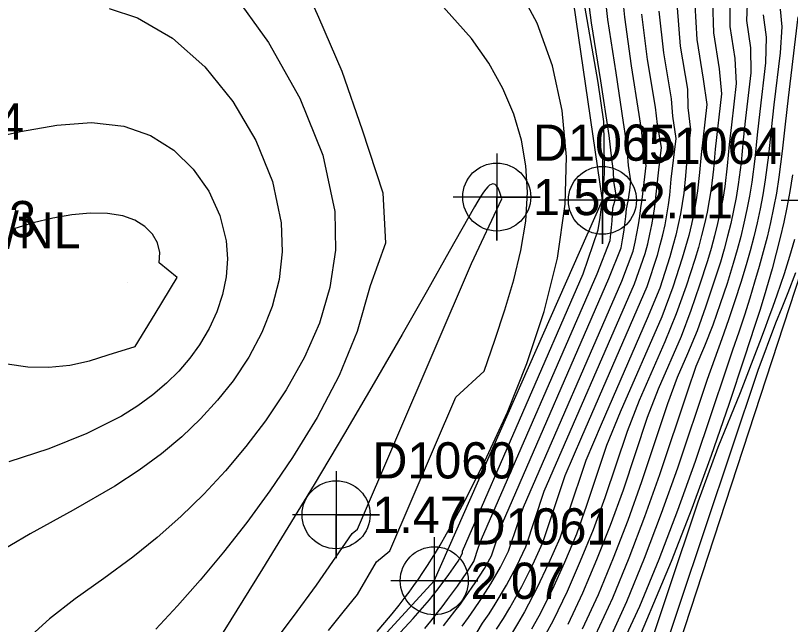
# Model space of a CAD drawing. Extents: x 2356077 to 2359823, y 225951 to 227822.
# Drawn here: x 2357294.1 to 2357347.5, y 226641.4 to 226683.4 of the extents above; entities that cross this region are included whole.
import ezdxf

# ---------------------------------------------------------------- set-up
doc = ezdxf.new("R2010")
doc.units = 0
for name, color, linetype in [('DTM Contours Major', 7, 'Continuous'), ('DTM Contours Minor', 7, 'Continuous'), ('Exist DTM Breakline', 7, 'Continuous'), ('Exist DTM Breakline Cogo Elevation', 7, 'Continuous'), ('Exist DTM Breakline Cogo Number', 7, 'Continuous'), ('Exist DTM Breakline Cogo Point CELL', 7, 'Continuous'), ('Exist DTM Regular Point CELL', 7, 'Continuous'), ('Exist DTM Regular Point Cogo Comment', 7, 'Continuous'), ('Exist DTM Regular Point Cogo Elevation', 7, 'Continuous'), ('Exist DTM Regular Point Cogo Number', 7, 'Continuous'), ('PH Exist DTM Point', 7, 'Continuous')]:
    doc.layers.add(name, color=color, linetype=linetype)

msp = doc.modelspace()

# ---------------------------------------------------------------- linework, layer by layer
at = {"layer": 'DTM Contours Major'}
for points in [[(2357319.049, 226640.927), (2357319.587, 226641.554), (2357320.091, 226642.163), (2357320.565, 226642.756), (2357320.915, 226643.208), (2357321.252, 226643.656), (2357321.578, 226644.103), (2357321.897, 226644.554), (2357322.21, 226645.013), (2357322.52, 226645.482), (2357322.956, 226646.169), (2357323.395, 226646.892), (2357323.842, 226647.66), (2357324.301, 226648.477), (2357324.776, 226649.353), (2357325.272, 226650.294), (2357326.622, 226652.988), (2357328.026, 226656.06), (2357329.375, 226659.424), (2357330.563, 226662.994), (2357331.482, 226666.682), (2357332.023, 226670.402), (2357332.112, 226673.676), (2357331.817, 226676.87), (2357331.138, 226679.948), (2357330.075, 226682.872), (2357328.628, 226685.605)], [(2357309.005, 226685.105), (2357311.567, 226681.55), (2357313.727, 226677.722), (2357315.307, 226673.785), (2357316.129, 226669.9), (2357316.175, 226667.223), (2357315.801, 226664.656), (2357315.07, 226662.199), (2357314.043, 226659.849), (2357312.783, 226657.607), (2357311.352, 226655.472), (2357310.01, 226653.701), (2357308.59, 226652.01), (2357307.095, 226650.401), (2357305.529, 226648.872), (2357303.898, 226647.426), (2357302.204, 226646.061), (2357300.2, 226644.584), (2357298.243, 226643.18), (2357296.461, 226641.814), (2357294.977, 226640.449), (2357293.906, 226639.06)], [(2357343.37, 226684.574), (2357343.373, 226682.645), (2357343.707, 226680.456), (2357343.809, 226678.734), (2357343.469, 226675.883), (2357343.31, 226674.517), (2357343.187, 226673.047), (2357343.009, 226671.613), (2357342.87, 226670.754), (2357342.708, 226669.904), (2357342.523, 226669.058), (2357342.314, 226668.209), (2357342.081, 226667.354), (2357341.825, 226666.487), (2357341.282, 226664.808), (2357340.668, 226663.069), (2357339.999, 226661.272), (2357338.425, 226657.649), (2357337.674, 226655.683), (2357336.003, 226650.689), (2357335.109, 226648.257), (2357334.173, 226645.873), (2357333.202, 226643.577), (2357332.188, 226641.412)], [(2357325.953, 226640.89), (2357326.319, 226641.502), (2357326.764, 226642.164), (2357327.187, 226642.827), (2357327.96, 226644.135), (2357328.677, 226645.466), (2357329.29, 226646.775), (2357330.574, 226650.611), (2357336.783, 226664.908), (2357337.534, 226667.007), (2357337.702, 226667.675), (2357337.85, 226668.33), (2357337.98, 226668.975), (2357338.091, 226669.613), (2357338.183, 226670.246), (2357338.476, 226672.759), (2357338.662, 226674.319), (2357338.369, 226675.898), (2357338.245, 226677.085), (2357337.693, 226680.388), (2357337.302, 226683.501)], [(2357347.677, 226672.436), (2357347.503, 226671.266), (2357347.301, 226670.174), (2357347.078, 226669.162), (2357346.835, 226668.093), (2357346.568, 226667.02), (2357346.276, 226665.934), (2357346.011, 226665.003), (2357345.726, 226664.049), (2357345.421, 226663.064), (2357345.096, 226662.039), (2357344.377, 226659.842), (2357343.29, 226656.598), (2357342.067, 226653.072), (2357340.735, 226649.413), (2357339.323, 226645.773), (2357336.395, 226638.819)]]:
    msp.add_lwpolyline(points, dxfattribs=at)
at = {"layer": 'DTM Contours Minor'}
for points in [[(2357322.347, 226641.139), (2357322.756, 226641.649), (2357323.151, 226642.152), (2357323.533, 226642.646), (2357323.902, 226643.134), (2357324.59, 226644.071), (2357325.239, 226644.994), (2357325.713, 226645.772), (2357326.041, 226646.753), (2357326.253, 226647.295), (2357334.207, 226665.601), (2357335.113, 226667.9), (2357335.168, 226668.351), (2357335.214, 226668.799), (2357335.251, 226669.247), (2357335.281, 226669.693), (2357335.302, 226670.14), (2357335.433, 226670.603), (2357335.516, 226671.184), (2357335.374, 226671.958), (2357335.333, 226672.672), (2357335.226, 226673.525), (2357335.041, 226675.142), (2357334.475, 226678.908), (2357333.819, 226682.911), (2357333.306, 226686.982)], [(2357323.617, 226641.32), (2357324.024, 226641.829), (2357324.414, 226642.333), (2357324.788, 226642.832), (2357325.148, 226643.33), (2357325.815, 226644.302), (2357326.442, 226645.281), (2357326.924, 226646.162), (2357327.408, 226647.609), (2357327.695, 226648.407), (2357335.03, 226665.288), (2357335.862, 226667.383), (2357335.965, 226667.932), (2357336.054, 226668.474), (2357336.13, 226669.011), (2357336.193, 226669.545), (2357336.244, 226670.076), (2357336.361, 226670.615), (2357336.462, 226671.366), (2357336.54, 226672.018), (2357336.37, 226673.068), (2357336.316, 226673.933), (2357336.184, 226674.965), (2357336.028, 226676.045), (2357335.522, 226679.467), (2357334.959, 226683.13), (2357334.54, 226686.877)], [(2357313.584, 226686.497), (2357315.009, 226683.305), (2357316.61, 226679.572), (2357318.028, 226675.528), (2357319.433, 226671.175), (2357319.621, 226667.715), (2357318.564, 226664.769), (2357317.675, 226661.622), (2357316.426, 226658.594), (2357314.909, 226655.692), (2357313.214, 226652.923), (2357311.66, 226650.629), (2357310.065, 226648.451), (2357308.455, 226646.398), (2357306.857, 226644.483), (2357305.297, 226642.715), (2357303.799, 226641.105)], [(2357324.915, 226641.313), (2357325.35, 226641.903), (2357325.765, 226642.489), (2357326.161, 226643.074), (2357326.887, 226644.218), (2357327.563, 226645.376), (2357328.107, 226646.468), (2357328.772, 226648.455), (2357329.137, 226649.519), (2357335.908, 226665.1), (2357336.697, 226667.163), (2357336.834, 226667.777), (2357336.955, 226668.38), (2357337.06, 226668.975), (2357337.148, 226669.565), (2357337.22, 226670.151), (2357337.31, 226670.73), (2357337.59, 226673.08), (2357337.373, 226674.389), (2357337.288, 226675.398), (2357337.124, 226676.575), (2357336.594, 226679.931), (2357336.117, 226683.305), (2357335.785, 226686.76)], [(2357320.358, 226640.576), (2357321.543, 226641.829), (2357322.663, 226643.131), (2357323.167, 226643.763), (2357323.663, 226644.42), (2357323.985, 226644.863), (2357324.307, 226645.321), (2357324.629, 226645.794), (2357324.854, 226646.16), (2357324.935, 226646.361), (2357324.936, 226646.472), (2357333.247, 226665.6), (2357334.282, 226668.643), (2357334.417, 226669.485), (2357334.494, 226670.042), (2357334.579, 226670.773), (2357334.623, 226671.225), (2357334.66, 226671.676), (2357334.69, 226672.127), (2357334.713, 226672.577), (2357334.73, 226673.028), (2357334.68, 226676.112), (2357334.277, 226678.799), (2357333.213, 226684.994)], [(2357344.57, 226684.762), (2357344.518, 226683.065), (2357344.79, 226681.184), (2357344.818, 226679.447), (2357344.446, 226676.333), (2357344.276, 226674.847), (2357344.134, 226673.284), (2357343.939, 226671.762), (2357343.792, 226670.855), (2357343.621, 226669.961), (2357343.428, 226669.074), (2357343.212, 226668.189), (2357342.973, 226667.3), (2357342.711, 226666.402), (2357342.226, 226664.876), (2357341.687, 226663.302), (2357341.101, 226661.675), (2357340.438, 226660.075), (2357339.732, 226658.45), (2357339.074, 226656.637), (2357337.271, 226651.251), (2357336.337, 226648.595), (2357335.329, 226645.984), (2357334.278, 226643.468), (2357333.176, 226641.104)], [(2357319.921, 226646.498), (2357324.479, 226657.088), (2357326.439, 226658.892), (2357327.164, 226661.026), (2357327.856, 226663.117), (2357328.471, 226665.175), (2357328.964, 226667.209), (2357329.292, 226669.228), (2357329.41, 226671.241), (2357329.306, 226673.035), (2357328.995, 226674.826), (2357328.47, 226676.607), (2357327.724, 226678.372), (2357326.752, 226680.115), (2357325.548, 226681.83), (2357323.236, 226684.414)], [(2357340.959, 226684.156), (2357341.094, 226681.761), (2357341.536, 226679.028), (2357341.788, 226677.28), (2357341.376, 226673.837), (2357341.272, 226672.586), (2357341.13, 226671.319), (2357341.014, 226670.553), (2357340.875, 226669.79), (2357340.712, 226669.024), (2357340.526, 226668.252), (2357340.318, 226667.469), (2357340.086, 226666.671), (2357339.44, 226664.682), (2357338.676, 226662.643), (2357335.812, 226656.05), (2357334.867, 226653.753), (2357333.486, 226649.627), (2357332.786, 226647.656), (2357331.965, 226645.701), (2357331.107, 226643.811), (2357330.193, 226642.001), (2357329.699, 226641.109)], [(2357342.165, 226684.37), (2357342.231, 226682.208), (2357342.623, 226679.733), (2357342.799, 226678.011), (2357342.342, 226674.184), (2357342.233, 226672.815), (2357342.073, 226671.466), (2357341.945, 226670.654), (2357341.793, 226669.848), (2357341.619, 226669.042), (2357341.42, 226668.231), (2357341.198, 226667.411), (2357340.953, 226666.577), (2357340.356, 226664.745), (2357339.672, 226662.837), (2357338.886, 226660.918), (2357337.122, 226656.858), (2357336.276, 226654.734), (2357334.744, 226650.157), (2357333.933, 226647.946), (2357333.054, 226645.779), (2357332.14, 226643.689), (2357331.176, 226641.703), (2357330.659, 226640.735)], [(2357300.589, 226683.898), (2357302.542, 226683.25), (2357304.948, 226681.842), (2357307.166, 226679.873), (2357309.108, 226677.481), (2357310.691, 226674.8), (2357311.829, 226671.966), (2357312.437, 226669.114), (2357312.508, 226667.125), (2357312.291, 226665.2), (2357311.815, 226663.344), (2357311.107, 226661.561), (2357310.199, 226659.855), (2357309.117, 226658.229), (2357308.055, 226656.883), (2357306.88, 226655.596), (2357305.588, 226654.365), (2357304.177, 226653.186), (2357302.642, 226652.054), (2357300.979, 226650.966), (2357298.096, 226649.299), (2357295.122, 226647.668), (2357292.302, 226646.007)], [(2357327.283, 226641.092), (2357327.754, 226641.827), (2357328.202, 226642.567), (2357329.022, 226644.039), (2357329.782, 226645.549), (2357330.472, 226647.079), (2357332.015, 226651.688), (2357333.16, 226654.362), (2357337.659, 226664.717), (2357338.379, 226666.881), (2357338.572, 226667.597), (2357338.745, 226668.299), (2357338.896, 226668.989), (2357339.027, 226669.671), (2357339.136, 226670.348), (2357339.224, 226671.024), (2357339.325, 226672.133), (2357339.658, 226674.923), (2357339.428, 226676.461), (2357339.353, 226677.668), (2357338.808, 226680.838), (2357338.497, 226683.711)], [(2357339.724, 226683.939), (2357339.943, 226681.306), (2357340.448, 226678.327), (2357340.468, 226677.078), (2357340.654, 226675.521), (2357340.41, 226673.479), (2357340.301, 226672.358), (2357340.181, 226671.17), (2357340.078, 226670.449), (2357339.953, 226669.729), (2357339.805, 226669.005), (2357339.635, 226668.273), (2357339.443, 226667.529), (2357339.228, 226666.77), (2357338.539, 226664.619), (2357337.665, 226662.523), (2357334.491, 226655.219), (2357333.446, 226652.737), (2357332.226, 226649.092), (2357331.641, 226647.376), (2357330.874, 226645.626), (2357330.068, 226643.93), (2357329.202, 226642.29), (2357328.731, 226641.474), (2357328.237, 226640.669)], [(2357346.825, 226683.846), (2357346.959, 226682.625), (2357346.831, 226680.827), (2357346.405, 226677.262), (2357346.21, 226675.547), (2357346.028, 226673.791), (2357345.801, 226672.086), (2357345.641, 226671.052), (2357345.451, 226670.091), (2357345.244, 226669.12), (2357345.016, 226668.156), (2357344.766, 226667.192), (2357344.493, 226666.223), (2357344.121, 226664.991), (2357343.716, 226663.727), (2357343.279, 226662.42), (2357342.807, 226661.112), (2357342.313, 226659.708), (2357341.793, 226658.306), (2357339.753, 226652.21), (2357338.638, 226649.075), (2357337.463, 226645.964), (2357336.237, 226642.973), (2357334.969, 226640.2)], [(2357345.669, 226683.467), (2357345.873, 226681.911), (2357345.826, 226680.147), (2357345.425, 226676.793), (2357345.243, 226675.19), (2357345.081, 226673.532), (2357344.87, 226671.92), (2357344.716, 226670.953), (2357344.535, 226670.024), (2357344.335, 226669.096), (2357344.112, 226668.173), (2357343.867, 226667.248), (2357343.599, 226666.317), (2357343.17, 226664.939), (2357342.699, 226663.522), (2357342.189, 226662.057), (2357341.627, 226660.604), (2357341.019, 226659.204), (2357340.442, 226657.498), (2357338.516, 226651.741), (2357337.487, 226648.848), (2357336.4, 226645.99), (2357335.267, 226643.238), (2357334.09, 226640.668)], [(2357348.049, 226683.314), (2357347.385, 226677.73), (2357347.174, 226675.914), (2357346.975, 226674.063), (2357346.735, 226672.263), (2357346.57, 226671.156), (2357346.373, 226670.159), (2357346.16, 226669.145), (2357345.926, 226668.135), (2357345.67, 226667.125), (2357345.392, 226666.108), (2357345.075, 226665.023), (2357344.733, 226663.91), (2357344.366, 226662.76), (2357343.973, 226661.588), (2357343.555, 226660.324), (2357343.112, 226659.019), (2357342.086, 226655.951), (2357340.965, 226652.657), (2357339.755, 226649.271), (2357338.475, 226645.9), (2357337.138, 226642.667), (2357335.76, 226639.698)], [(2357291.9, 226674.832), (2357294.457, 226675.418), (2357296.968, 226675.86), (2357299.369, 226676.028), (2357301.596, 226675.792), (2357303.424, 226675.144), (2357305.028, 226674.128), (2357306.379, 226672.818), (2357307.451, 226671.291), (2357308.215, 226669.619), (2357308.643, 226667.88), (2357308.733, 226666.628), (2357308.647, 226665.388), (2357308.399, 226664.167), (2357308.002, 226662.975), (2357307.466, 226661.818), (2357306.806, 226660.705), (2357306.138, 226659.779), (2357305.382, 226658.893), (2357304.536, 226658.05), (2357303.598, 226657.25), (2357302.564, 226656.496), (2357301.432, 226655.788), (2357299.045, 226654.582), (2357296.418, 226653.534), (2357293.669, 226652.634)], [(2357317.686, 226648.002), (2357325.566, 226666.309), (2357327.64, 226670.773), (2357327.51, 226671.202), (2357327.44, 226671.393), (2357327.369, 226671.542), (2357327.33, 226671.607), (2357327.288, 226671.663), (2357327.244, 226671.711), (2357327.195, 226671.749), (2357327.113, 226671.787), (2357327.02, 226671.795), (2357326.917, 226671.768), (2357326.803, 226671.704), (2357326.677, 226671.597), (2357326.539, 226671.445), (2357326.375, 226671.227), (2357326.192, 226670.951), (2357325.987, 226670.615), (2357325.756, 226670.22), (2357324.02, 226667.134), (2357322.522, 226664.483), (2357320.777, 226661.42), (2357318.85, 226658.078), (2357316.806, 226654.586), (2357314.712, 226651.075), (2357312.901, 226648.102), (2357311.15, 226645.265), (2357308.015, 226640.213)], [(2357303.752, 226662.851), (2357305.257, 226665.356), (2357304.016, 226666.35), (2357304.072, 226667.065), (2357303.916, 226667.737), (2357303.565, 226668.345), (2357303.036, 226668.87), (2357302.346, 226669.292), (2357301.514, 226669.593), (2357300.457, 226669.766), (2357299.28, 226669.787), (2357298.015, 226669.672), (2357296.692, 226669.44), (2357295.343, 226669.108), (2357293.999, 226668.693)], [(2357347.812, 226667.97), (2357347.473, 226666.803), (2357347.099, 226665.607), (2357346.857, 226664.872), (2357346.6, 226664.118), (2357346.327, 226663.343), (2357346.039, 226662.543), (2357345.733, 226661.715), (2357345.41, 226660.854), (2357344.065, 226657.392), (2357342.535, 226653.613), (2357341.168, 226649.851), (2357337.027, 226637.479)], [(2357347.889, 226665.679), (2357347.36, 226664.288), (2357346.95, 226663.262), (2357346.507, 226662.188), (2357345.289, 226658.936), (2357338.029, 226637.245), (2357337.662, 226637.198), (2357337.68, 226636.425), (2357337.297, 226635.72), (2357337.161, 226635.325), (2357337.318, 226634.718), (2357337.645, 226633.954), (2357338.102, 226633.227), (2357338.681, 226632.524), (2357339.374, 226631.829), (2357340.172, 226631.126), (2357341.044, 226630.654), (2357344.251, 226629.129), (2357355.019, 226621.181)], [(2357293.542, 226659.388), (2357294.968, 226659.177), (2357296.421, 226659.154), (2357297.858, 226659.299), (2357299.234, 226659.595), (2357300.505, 226660.022), (2357302.38, 226660.579), (2357303.752, 226662.851)], [(2357311.746, 226639.93), (2357313.282, 226641.961), (2357314.874, 226644.121), (2357317.328, 226647.704), (2357317.686, 226648.002)], [(2357315.699, 226641.016), (2357316.714, 226642.266), (2357317.69, 226643.498), (2357319.017, 226645.743), (2357319.921, 226646.498)]]:
    msp.add_lwpolyline(points, dxfattribs=at)
at = {"layer": 'Exist DTM Breakline'}
for points in [[(2357281.817, 226596.55), (2357301.263, 226620.711), (2357322.988, 226644.434), (2357334.581, 226670.667), (2357330.12, 226701.283)], [(2357291.589, 226581.758), (2357314.878, 226607.468), (2357338.676, 226636.367), (2357349.898, 226670.663), (2357351.861, 226686.877)]]:
    msp.add_lwpolyline(points, dxfattribs=at)
at = {"layer": 'Exist DTM Breakline Cogo Point CELL'}
for points in [[(2357334.581, 226673.667), (2357334.581, 226667.667), (2357334.581, 226670.667), (2357337.581, 226670.667), (2357331.581, 226670.667)], [(2357349.898, 226673.663), (2357349.898, 226667.663), (2357349.898, 226670.663), (2357352.898, 226670.663), (2357346.898, 226670.663)], [(2357322.988, 226647.434), (2357322.988, 226641.434), (2357322.988, 226644.434), (2357325.988, 226644.434), (2357319.988, 226644.434)]]:
    msp.add_lwpolyline(points, dxfattribs=at)
for centre in [(2357334.581, 226670.667), (2357322.988, 226644.434)]:
    msp.add_circle(centre, 2.344, dxfattribs=at)
at = {"layer": 'Exist DTM Regular Point CELL'}
for points in [[(2357327.292, 226673.895), (2357327.292, 226667.895), (2357327.292, 226670.895), (2357330.292, 226670.895), (2357324.292, 226670.895)], [(2357316.223, 226651.987), (2357316.223, 226645.987), (2357316.223, 226648.987), (2357319.223, 226648.987), (2357313.223, 226648.987)]]:
    msp.add_lwpolyline(points, dxfattribs=at)
for centre in [(2357327.292, 226670.895), (2357316.223, 226648.987)]:
    msp.add_circle(centre, 2.344, dxfattribs=at)
at = {"layer": 'PH Exist DTM Point'}
msp.add_line((2357301.825, 226664.992), (2357301.825, 226664.992), dxfattribs=at)

# ---------------------------------------------------------------- texts
at = {"layer": 'Exist DTM Breakline Cogo Elevation'}
for s, p in [('2.11', (2357337.081, 226669.417)), ('2.07', (2357325.488, 226643.184))]:
    msp.add_text(s, height=2.5, dxfattribs=at).set_placement(p)
at = {"layer": 'Exist DTM Breakline Cogo Number'}
for s, p in [('D1064', (2357337.081, 226673.167)), ('D1043', (2357285.691, 226668.122)), ('D1061', (2357325.488, 226646.934))]:
    msp.add_text(s, height=2.5, dxfattribs=at).set_placement(p)
at = {"layer": 'Exist DTM Regular Point Cogo Comment'}
msp.add_text('TRV/NL', height=2.5, dxfattribs=at).set_placement((2357286.732, 226667.348))
at = {"layer": 'Exist DTM Regular Point Cogo Elevation'}
for s, p in [('1.58', (2357329.792, 226669.645)), ('1.47', (2357318.723, 226647.737))]:
    msp.add_text(s, height=2.5, dxfattribs=at).set_placement(p)
at = {"layer": 'Exist DTM Regular Point Cogo Number'}
for s, p in [('D614', (2357286.732, 226674.848)), ('D1065', (2357329.792, 226673.395)), ('D1060', (2357318.723, 226651.487))]:
    msp.add_text(s, height=2.5, dxfattribs=at).set_placement(p)

doc.saveas('drawing.dxf')
